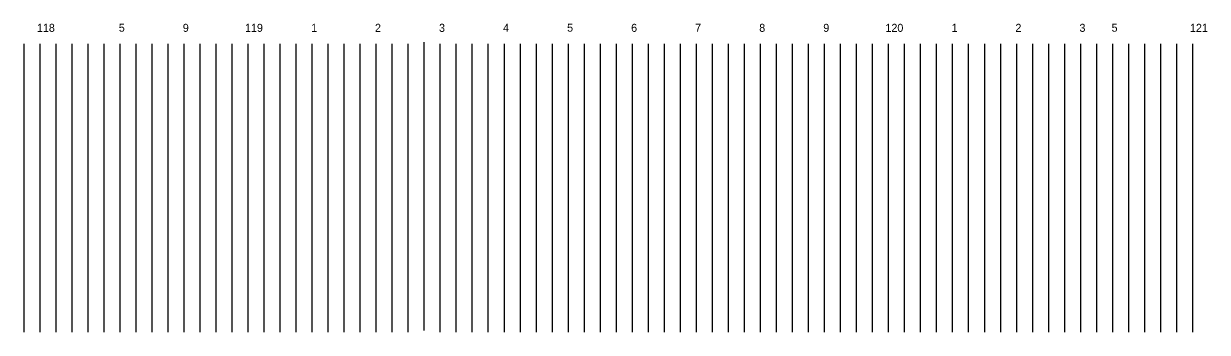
# Model space of a CAD drawing. Extents: x -1424 to 5155, y -2900 to 2050.
# Drawn here: x 2360 to 3099, y -2900 to -2707 of the extents above; entities that cross this region are included whole.
import ezdxf

# ---------------------------------------------------------------- set-up
doc = ezdxf.new("R2010")
doc.units = 0
doc.layers.add('NAVRHOVANÉ', color=7, linetype='Continuous')

msp = doc.modelspace()

# ---------------------------------------------------------------- linework, layer by layer
at = {"layer": 'NAVRHOVANÉ'}
for p, q in [((2360, -2720), (2360, -2900)), ((2370, -2720), (2370, -2900)), ((2380, -2720), (2380, -2900)), ((2390, -2720), (2390, -2900)), ((2400, -2720), (2400, -2900)), ((2410, -2720), (2410, -2900)), ((2420, -2720), (2420, -2900)), ((2430, -2720), (2430, -2900)), ((2440, -2720), (2440, -2900)), ((2450, -2720), (2450, -2900)), ((2460, -2720), (2460, -2900)), ((2470, -2720), (2470, -2900)), ((2480, -2720), (2480, -2900)), ((2490, -2720), (2490, -2900)), ((2500, -2720), (2500, -2900)), ((2510, -2720), (2510, -2900)), ((2520, -2720), (2520, -2900)), ((2530, -2720), (2530, -2900)), ((2540, -2720), (2540, -2900)), ((2550, -2720), (2550, -2900)), ((2560, -2720), (2560, -2900)), ((2570, -2720), (2570, -2900)), ((2580, -2720), (2580, -2900)), ((2590, -2720), (2590, -2900)), ((2600, -2720), (2600, -2900)), ((2609.97, -2718.88), (2609.97, -2898.88)), ((2620, -2720), (2620, -2900)), ((2630, -2720), (2630, -2900)), ((2640, -2720), (2640, -2900)), ((2650, -2720), (2650, -2900)), ((2660, -2720), (2660, -2900)), ((2670, -2720), (2670, -2900)), ((2680, -2720), (2680, -2900)), ((2690, -2720), (2690, -2900)), ((2700, -2720), (2700, -2900)), ((2710, -2720), (2710, -2900)), ((2720, -2720), (2720, -2900)), ((2730, -2720), (2730, -2900)), ((2740, -2720), (2740, -2900)), ((2750, -2720), (2750, -2900)), ((2760, -2720), (2760, -2900)), ((2770, -2720), (2770, -2900)), ((2780, -2720), (2780, -2900)), ((2790, -2720), (2790, -2900)), ((2800, -2720), (2800, -2900)), ((2810, -2720), (2810, -2900)), ((2820, -2720), (2820, -2900)), ((2830, -2720), (2830, -2900)), ((2840, -2720), (2840, -2900)), ((2850, -2720), (2850, -2900)), ((2860, -2720), (2860, -2900)), ((2870, -2720), (2870, -2900)), ((2880, -2720), (2880, -2900)), ((2890, -2720), (2890, -2900)), ((2900, -2720), (2900, -2900)), ((2910, -2720), (2910, -2900)), ((2920, -2720), (2920, -2900)), ((2930, -2720), (2930, -2900)), ((2940, -2720), (2940, -2900)), ((2950, -2720), (2950, -2900)), ((2960, -2720), (2960, -2900)), ((2970, -2720), (2970, -2900)), ((2980, -2720), (2980, -2900)), ((2990, -2720), (2990, -2900)), ((3000, -2720), (3000, -2900)), ((3010, -2720), (3010, -2900)), ((3020, -2720), (3020, -2900)), ((3030, -2720), (3030, -2900)), ((3040, -2720), (3040, -2900)), ((3050, -2720), (3050, -2900)), ((3060, -2720), (3060, -2900)), ((3070, -2720), (3070, -2900)), ((3080, -2720), (3080, -2900)), ((3090, -2720), (3090, -2900))]:
    msp.add_line(p, q, dxfattribs=at)

# ---------------------------------------------------------------- texts
for s, p in [('118', (2368.3, -2712.5)), ('5', (2419.41, -2712.42)), ('9', (2459.41, -2712.5)), ('119', (2498.25, -2712.5)), ('1', (2539.56, -2712.5)), ('2', (2579.42, -2712.5)), ('3', (2619.41, -2712.5)), ('4', (2659.42, -2712.48)), ('5', (2699.41, -2712.42)), ('6', (2739.41, -2712.5)), ('7', (2779.41, -2712.42)), ('8', (2819.41, -2712.5)), ('9', (2859.41, -2712.5)), ('120', (2898.25, -2712.5)), ('1', (2939.56, -2712.5)), ('2', (2979.42, -2712.5)), ('3', (3019.41, -2712.5)), ('5', (3039.46, -2712.42)), ('121', (3088.45, -2712.5))]:
    msp.add_text(s, height=5).set_placement(p)

doc.saveas('drawing.dxf')
